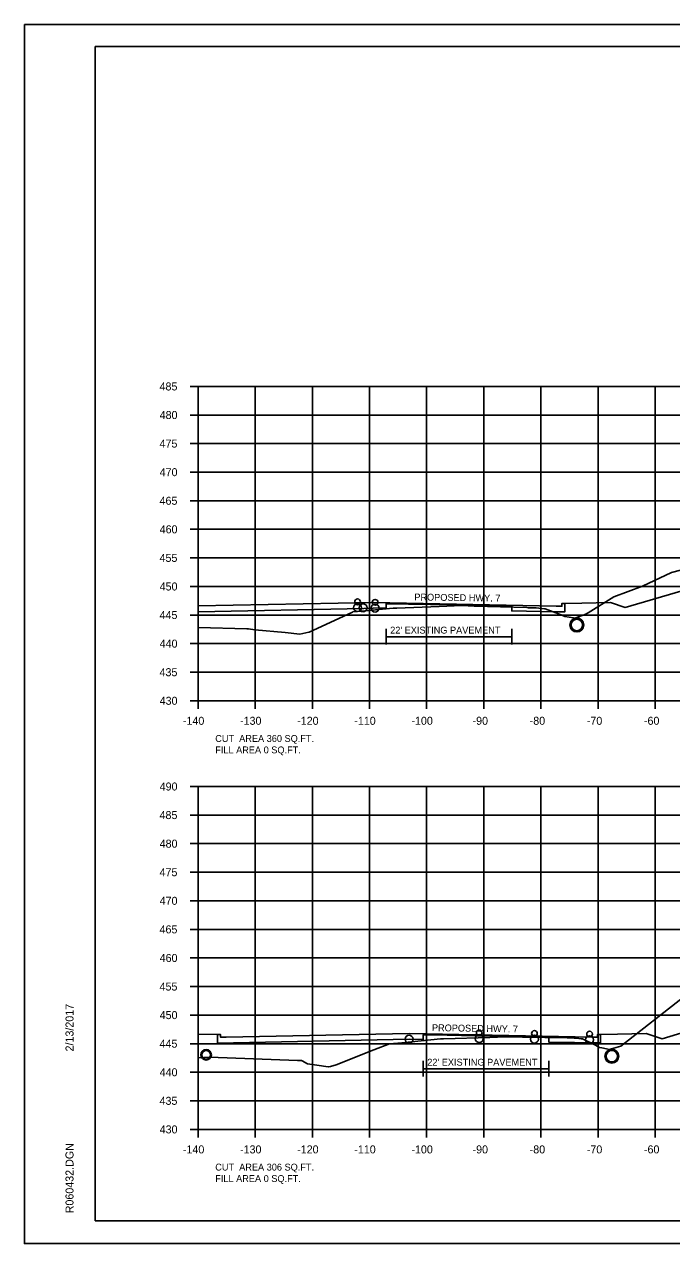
# Model space of a CAD drawing. Extents: x 1538688 to 1540766, y 656250 to 671912.
# Drawn here: x 1539203.7 to 1539317, y 656551.2 to 656764.6 of the extents above; entities that cross this region are included whole.
import ezdxf

# ---------------------------------------------------------------- set-up
doc = ezdxf.new("R2010")
doc.units = 0
for name, color, linetype in [('16', 7, 'Continuous'), ('18', 7, 'Continuous'), ('20', 7, 'Continuous'), ('22', 7, 'Continuous'), ('26', 7, 'Continuous'), ('39', 7, 'Continuous'), ('7', 7, 'Continuous'), ('Borings', 7, 'Continuous'), ('Default', 7, 'Continuous'), ('Horizontal Alignment', 7, 'Continuous'), ('RipRap', 7, 'Continuous'), ('Wall Heights', 7, 'Continuous')]:
    doc.layers.add(name, color=color, linetype=linetype)

msp = doc.modelspace()

# ---------------------------------------------------------------- linework, layer by layer
at = {"layer": '18'}
for points in [[(1539234.13, 656659.03), (1539234.19, 656659.02), (1539242.68, 656658.82), (1539242.93, 656658.8), (1539244.08, 656658.66), (1539249.39, 656658.14), (1539251.91, 656657.89), (1539253.53, 656658.21), (1539253.59, 656658.23), (1539254.19, 656658.49), (1539261.14, 656661.7), (1539261.14, 656661.75), (1539261.24, 656661.8), (1539263.33, 656661.98), (1539268.29, 656662.42), (1539268.64, 656662.43), (1539268.9, 656662.44), (1539276.33, 656662.72), (1539280.29, 656662.87), (1539282.44, 656662.78), (1539291.67, 656662.52), (1539291.68, 656662.52), (1539291.91, 656662.51), (1539293.28, 656662.47), (1539293.33, 656662.47), (1539294.77, 656662.31), (1539294.86, 656662.29), (1539297.7, 656661.23), (1539298.34, 656660.98), (1539299.82, 656660.75), (1539300.06, 656660.7), (1539301.99, 656661.38), (1539302.08, 656661.41), (1539302.41, 656661.63), (1539306.91, 656664.43), (1539311.9, 656666.27), (1539317.01, 656668.65), (1539324.38, 656670.59)], [(1539234.13, 656583.81), (1539235.15, 656583.77), (1539235.27, 656583.79), (1539236.1, 656583.85), (1539251.52, 656583.3), (1539252.22, 656583.28), (1539252.36, 656583.2), (1539253.29, 656582.71), (1539254.9, 656582.46), (1539256.91, 656582.14), (1539257.33, 656582.25), (1539258.29, 656582.52), (1539264.9, 656585.15), (1539267.65, 656586.21), (1539269.77, 656586.39), (1539276.54, 656587.04), (1539276.71, 656587.04), (1539277.11, 656587.07), (1539285.22, 656587.32), (1539287.89, 656587.4), (1539290.91, 656587.35), (1539298.74, 656587.25), (1539299.94, 656587.21), (1539300.34, 656587.2), (1539301.19, 656587.09), (1539301.42, 656587.06), (1539303.71, 656585.94), (1539304.41, 656585.58), (1539304.78, 656585.51), (1539306.16, 656585.21), (1539306.49, 656585.32), (1539308.12, 656585.78), (1539319.18, 656594.42)]]:
    msp.add_lwpolyline(points, dxfattribs=at)
for centre, radius in [((1539300.43, 656659.48), 1.21), ((1539235.53, 656584.28), 0.917), ((1539306.55, 656584.02), 1.21)]:
    msp.add_circle(centre, radius, dxfattribs=at)
at = {"layer": '20'}
for points in [[(1539306.31, 656663.42), (1539308.89, 656662.56), (1539353.22, 656675.52)], [(1539234.13, 656662.81), (1539264.8, 656663.42), (1539296.8, 656662.78), (1539297.8, 656662.76), (1539297.81, 656663.26), (1539298.31, 656663.26), (1539301.31, 656663.32), (1539306.31, 656663.42)], [(1539312.56, 656588), (1539315.37, 656587.06), (1539348.5, 656597.16)], [(1539234.13, 656587.9), (1539237.54, 656587.84), (1539238.04, 656587.84), (1539238.05, 656587.34), (1539239.05, 656587.36), (1539271.05, 656588), (1539303.05, 656587.36), (1539304.05, 656587.34), (1539304.06, 656587.84), (1539304.56, 656587.84), (1539307.56, 656587.9), (1539312.56, 656588)]]:
    msp.add_lwpolyline(points, dxfattribs=at)
at = {"layer": '22'}
for p, q in [((1539234.13, 656701.22), (1539514.13, 656701.22)), ((1539234.13, 656646.22), (1539234.13, 656701.22)), ((1539244.13, 656646.22), (1539244.13, 656701.22)), ((1539254.13, 656646.22), (1539254.13, 656701.22)), ((1539264.13, 656646.22), (1539264.13, 656701.22)), ((1539274.13, 656646.22), (1539274.13, 656701.22)), ((1539284.13, 656646.22), (1539284.13, 656701.22)), ((1539294.13, 656646.22), (1539294.13, 656701.22)), ((1539304.13, 656646.22), (1539304.13, 656701.22)), ((1539314.13, 656646.22), (1539314.13, 656701.22)), ((1539234.13, 656696.22), (1539514.13, 656696.22)), ((1539234.13, 656691.22), (1539514.13, 656691.22)), ((1539234.13, 656686.22), (1539514.13, 656686.22)), ((1539234.13, 656681.22), (1539514.13, 656681.22)), ((1539234.13, 656676.22), (1539514.13, 656676.22)), ((1539234.13, 656671.22), (1539514.13, 656671.22)), ((1539234.13, 656666.22), (1539514.13, 656666.22)), ((1539233.13, 656661.22), (1539514.13, 656661.22)), ((1539234.13, 656656.22), (1539514.13, 656656.22)), ((1539234.13, 656651.22), (1539514.13, 656651.22)), ((1539234.13, 656646.22), (1539514.13, 656646.22)), ((1539234.13, 656631.22), (1539514.13, 656631.22)), ((1539234.13, 656571.22), (1539234.13, 656631.22)), ((1539234.13, 656631.22), (1539514.13, 656631.22)), ((1539234.13, 656571.22), (1539234.13, 656631.22)), ((1539244.13, 656571.22), (1539244.13, 656631.22)), ((1539244.13, 656571.22), (1539244.13, 656631.22)), ((1539254.13, 656571.22), (1539254.13, 656631.22)), ((1539254.13, 656571.22), (1539254.13, 656631.22)), ((1539264.13, 656571.22), (1539264.13, 656631.22)), ((1539264.13, 656571.22), (1539264.13, 656631.22)), ((1539274.13, 656571.22), (1539274.13, 656631.22)), ((1539274.13, 656571.22), (1539274.13, 656631.22)), ((1539284.13, 656571.22), (1539284.13, 656631.22)), ((1539284.13, 656571.22), (1539284.13, 656631.22)), ((1539294.13, 656571.22), (1539294.13, 656631.22)), ((1539294.13, 656571.22), (1539294.13, 656631.22)), ((1539304.13, 656571.22), (1539304.13, 656631.22)), ((1539304.13, 656571.22), (1539304.13, 656631.22)), ((1539314.13, 656571.22), (1539314.13, 656631.22)), ((1539314.13, 656571.22), (1539314.13, 656631.22)), ((1539234.13, 656626.22), (1539514.13, 656626.22)), ((1539234.13, 656626.22), (1539514.13, 656626.22)), ((1539234.13, 656621.22), (1539514.13, 656621.22)), ((1539234.13, 656621.22), (1539514.13, 656621.22)), ((1539234.13, 656616.22), (1539514.13, 656616.22)), ((1539234.13, 656616.22), (1539514.13, 656616.22)), ((1539234.13, 656611.22), (1539514.13, 656611.22)), ((1539234.13, 656611.22), (1539514.13, 656611.22)), ((1539234.13, 656606.22), (1539514.13, 656606.22)), ((1539234.13, 656606.22), (1539514.13, 656606.22)), ((1539234.13, 656601.22), (1539514.13, 656601.22)), ((1539234.13, 656601.22), (1539514.13, 656601.22)), ((1539234.13, 656596.22), (1539514.13, 656596.22)), ((1539234.13, 656596.22), (1539514.13, 656596.22)), ((1539234.13, 656591.22), (1539514.13, 656591.22)), ((1539234.13, 656591.22), (1539514.13, 656591.22)), ((1539234.13, 656586.22), (1539514.13, 656586.22)), ((1539234.13, 656586.22), (1539514.13, 656586.22)), ((1539234.13, 656581.22), (1539514.13, 656581.22)), ((1539234.13, 656581.22), (1539514.13, 656581.22)), ((1539234.13, 656576.22), (1539514.13, 656576.22)), ((1539234.13, 656576.22), (1539514.13, 656576.22)), ((1539234.13, 656571.22), (1539514.13, 656571.22)), ((1539234.13, 656571.22), (1539514.13, 656571.22))]:
    msp.add_line(p, q, dxfattribs=at)
at = {"layer": '26'}
for p, q in [((1539203.73, 656764.57), (1539537.06, 656764.57)), ((1539203.73, 656551.24), (1539537.06, 656551.24))]:
    msp.add_line(p, q, dxfattribs=at)
msp.add_lwpolyline([(1539203.72, 656764.57), (1539537.06, 656764.57), (1539537.06, 656551.24), (1539203.72, 656551.24)], close=True, dxfattribs=at)
for centre, radius in [((1539262.05, 656663.53), 0.5), ((1539265.1, 656663.45), 0.5), ((1539262.05, 656662.53), 0.7), ((1539263.01, 656662.5), 0.7), ((1539265.1, 656662.45), 0.7), ((1539271.05, 656587), 0.7), ((1539283.34, 656587.11), 0.7), ((1539283.34, 656588.11), 0.5), ((1539293, 656587.01), 0.7), ((1539293, 656588.01), 0.5), ((1539302.66, 656586.9), 0.7), ((1539302.66, 656587.9), 0.5)]:
    msp.add_circle(centre, radius, dxfattribs=at)
at = {"layer": '39'}
for centre, radius in [((1539300.43, 656659.48), 1), ((1539235.53, 656584.28), 0.75), ((1539306.55, 656584.02), 1)]:
    msp.add_circle(centre, radius, dxfattribs=at)
at = {"layer": '7'}
for p, q in [((1539267.04, 656658.79), (1539267.04, 656656.04)), ((1539289.04, 656657.42), (1539267.04, 656657.42)), ((1539289.04, 656658.79), (1539289.04, 656656.04)), ((1539273.53, 656583.2), (1539273.53, 656580.45)), ((1539295.53, 656583.2), (1539295.53, 656580.45)), ((1539295.53, 656581.82), (1539273.53, 656581.82))]:
    msp.add_line(p, q, dxfattribs=at)
at = {"layer": 'Borings'}
for p, q in [((1539232.73, 656701.22), (1539234.13, 656701.22)), ((1539234.13, 656646.22), (1539234.13, 656701.22)), ((1539232.73, 656696.22), (1539234.13, 656696.22)), ((1539232.73, 656691.22), (1539234.13, 656691.22)), ((1539232.73, 656686.22), (1539234.13, 656686.22)), ((1539232.73, 656681.22), (1539234.13, 656681.22)), ((1539232.73, 656676.22), (1539234.13, 656676.22)), ((1539232.73, 656671.22), (1539234.13, 656671.22)), ((1539232.73, 656666.22), (1539234.13, 656666.22)), ((1539232.73, 656661.22), (1539234.13, 656661.22)), ((1539232.73, 656656.22), (1539234.13, 656656.22)), ((1539232.73, 656651.22), (1539234.13, 656651.22)), ((1539232.73, 656646.22), (1539234.13, 656646.22)), ((1539234.13, 656646.22), (1539514.13, 656646.22)), ((1539234.13, 656644.82), (1539234.13, 656646.22)), ((1539244.13, 656644.82), (1539244.13, 656646.22)), ((1539254.13, 656644.82), (1539254.13, 656646.22)), ((1539264.13, 656644.82), (1539264.13, 656646.22)), ((1539274.13, 656644.82), (1539274.13, 656646.22)), ((1539284.13, 656644.82), (1539284.13, 656646.22)), ((1539294.13, 656644.82), (1539294.13, 656646.22)), ((1539304.13, 656644.82), (1539304.13, 656646.22)), ((1539314.13, 656644.82), (1539314.13, 656646.22)), ((1539232.73, 656631.22), (1539234.13, 656631.22)), ((1539234.13, 656571.22), (1539234.13, 656631.22)), ((1539232.73, 656626.22), (1539234.13, 656626.22)), ((1539232.73, 656621.22), (1539234.13, 656621.22)), ((1539232.73, 656616.22), (1539234.13, 656616.22)), ((1539232.73, 656611.22), (1539234.13, 656611.22)), ((1539232.73, 656606.22), (1539234.13, 656606.22)), ((1539232.73, 656601.22), (1539234.13, 656601.22)), ((1539232.73, 656596.22), (1539234.13, 656596.22)), ((1539232.73, 656591.22), (1539234.13, 656591.22)), ((1539232.73, 656586.22), (1539234.13, 656586.22)), ((1539232.73, 656581.22), (1539234.13, 656581.22)), ((1539232.73, 656576.22), (1539234.13, 656576.22)), ((1539232.73, 656571.22), (1539234.13, 656571.22)), ((1539234.13, 656571.22), (1539514.13, 656571.22)), ((1539234.13, 656569.82), (1539234.13, 656571.22)), ((1539244.13, 656569.82), (1539244.13, 656571.22)), ((1539254.13, 656569.82), (1539254.13, 656571.22)), ((1539264.13, 656569.82), (1539264.13, 656571.22)), ((1539274.13, 656569.82), (1539274.13, 656571.22)), ((1539284.13, 656569.82), (1539284.13, 656571.22)), ((1539294.13, 656569.82), (1539294.13, 656571.22)), ((1539304.13, 656569.82), (1539304.13, 656571.22)), ((1539314.13, 656569.82), (1539314.13, 656571.22))]:
    msp.add_line(p, q, dxfattribs=at)
at = {"layer": 'Default'}
for p, q in [((1539273.53, 656586.95), (1539273.53, 656587.78)), ((1539295.53, 656586.51), (1539295.53, 656587.34))]:
    msp.add_line(p, q, dxfattribs=at)
at = {"layer": 'RipRap'}
for p, q in [((1539216.13, 656760.68), (1539532.31, 656760.68)), ((1539216.13, 656555.22), (1539216.13, 656760.68)), ((1539216.13, 656555.22), (1539216.13, 656555.22)), ((1539532.31, 656555.22), (1539216.13, 656555.22))]:
    msp.add_line(p, q, dxfattribs=at)
at = {"layer": 'Wall Heights'}
for points in [[(1539298.31, 656663.26), (1539298.31, 656661.76), (1539296.8, 656661.78), (1539296.8, 656661.78), (1539289.04, 656661.94), (1539289.04, 656662.77), (1539274.8, 656663.06), (1539267.04, 656663.21), (1539267.04, 656662.47), (1539264.8, 656662.42), (1539263.13, 656662.39), (1539234.13, 656661.81)], [(1539304.56, 656587.84), (1539304.56, 656586.34), (1539295.53, 656586.46), (1539295.53, 656587.34), (1539285.2, 656587.55), (1539275.2, 656587.75), (1539273.53, 656587.78), (1539273.53, 656586.95), (1539271.05, 656587), (1539237.54, 656586.33), (1539237.54, 656587.84)]]:
    msp.add_lwpolyline(points, dxfattribs=at)

# ---------------------------------------------------------------- texts
at = {"layer": '16'}
for rotation, p in [(359.1891, (1539271.97, 656663.78)), (359.1307, (1539275.05, 656588.42))]:
    msp.add_text('PROPOSED HWY. 7', height=1.2, rotation=rotation, dxfattribs=at).set_placement(p)
at = {"layer": '7'}
for p in [(1539267.75, 656657.98), (1539274.24, 656582.38)]:
    msp.add_text("22' EXISTING PAVEMENT", height=1.2, dxfattribs=at).set_placement(p)
at = {"layer": 'Horizontal Alignment'}
for s, height, p in [('485', 1.4, (1539227.38, 656700.52)), ('480', 1.4, (1539227.4, 656695.52)), ('475', 1.4, (1539227.38, 656690.52)), ('470', 1.4, (1539227.4, 656685.52)), ('465', 1.4, (1539227.38, 656680.52)), ('460', 1.4, (1539227.4, 656675.52)), ('455', 1.4, (1539227.38, 656670.52)), ('450', 1.4, (1539227.4, 656665.52)), ('445', 1.4, (1539227.38, 656660.52)), ('440', 1.4, (1539227.4, 656655.52)), ('435', 1.4, (1539227.38, 656650.52)), ('430', 1.4, (1539227.4, 656645.52)), ('-140', 1.4, (1539231.47, 656642.02)), ('-130', 1.4, (1539241.47, 656642.02)), ('-120', 1.4, (1539251.47, 656642.02)), ('-110', 1.4, (1539261.47, 656642.02)), ('-100', 1.4, (1539271.47, 656642.02)), ('-90', 1.4, (1539282.17, 656642.02)), ('-80', 1.4, (1539292.17, 656642.02)), ('-70', 1.4, (1539302.17, 656642.02)), ('-60', 1.4, (1539312.17, 656642.02)), ('CUT  AREA 360 SQ.FT.', 1.2, (1539237.13, 656639.02)), ('FILL AREA 0 SQ.FT.', 1.2, (1539237.13, 656637.02)), ('490', 1.4, (1539227.4, 656630.52)), ('485', 1.4, (1539227.38, 656625.52)), ('480', 1.4, (1539227.4, 656620.52)), ('475', 1.4, (1539227.38, 656615.52)), ('470', 1.4, (1539227.4, 656610.52)), ('465', 1.4, (1539227.38, 656605.52)), ('460', 1.4, (1539227.4, 656600.52)), ('455', 1.4, (1539227.38, 656595.52)), ('450', 1.4, (1539227.4, 656590.52)), ('445', 1.4, (1539227.38, 656585.52)), ('440', 1.4, (1539227.4, 656580.52)), ('435', 1.4, (1539227.38, 656575.52)), ('430', 1.4, (1539227.4, 656570.52)), ('-140', 1.4, (1539231.47, 656567.02)), ('-130', 1.4, (1539241.47, 656567.02)), ('-120', 1.4, (1539251.47, 656567.02)), ('-110', 1.4, (1539261.47, 656567.02)), ('-100', 1.4, (1539271.47, 656567.02)), ('-90', 1.4, (1539282.17, 656567.02)), ('-80', 1.4, (1539292.17, 656567.02)), ('-70', 1.4, (1539302.17, 656567.02)), ('-60', 1.4, (1539312.17, 656567.02)), ('CUT  AREA 306 SQ.FT.', 1.2, (1539237.13, 656564.02)), ('FILL AREA 0 SQ.FT.', 1.2, (1539237.13, 656562.02))]:
    msp.add_text(s, height=height, dxfattribs=at).set_placement(p)
at = {"layer": 'RipRap'}
for s, p in [('2/13/2017', (1539212.32, 656584.86)), ('R060432.DGN', (1539212.32, 656556.54))]:
    msp.add_text(s, height=1.4, rotation=90, dxfattribs=at).set_placement(p)

doc.saveas('drawing.dxf')
